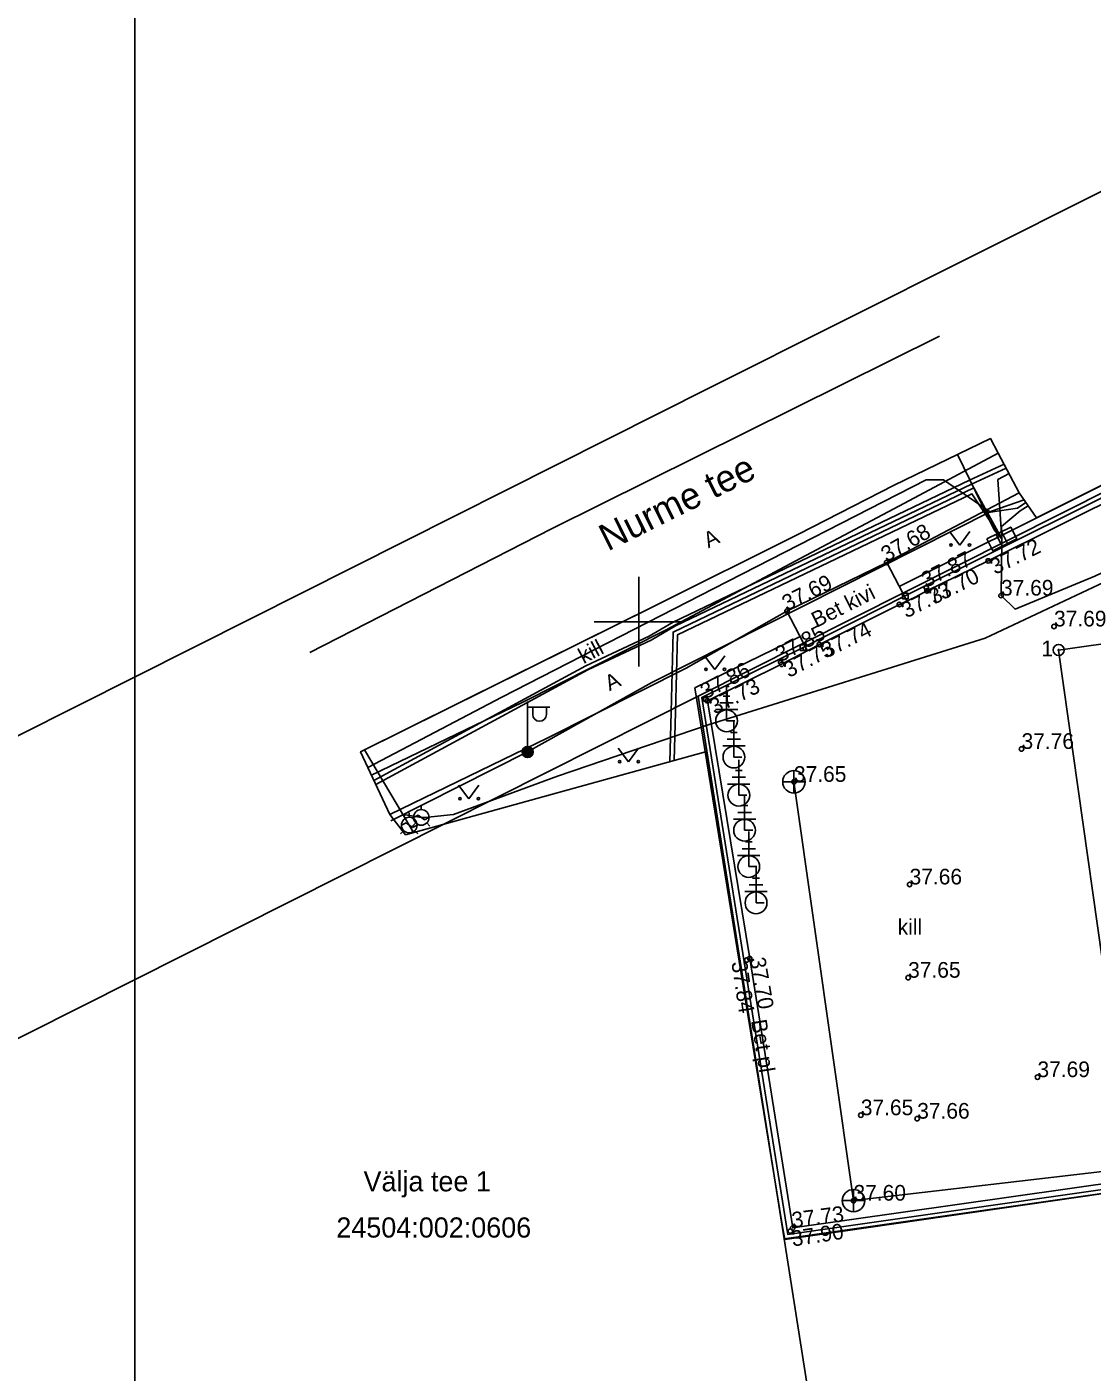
# Model space of a CAD drawing. Extents: x 551828 to 552309, y 6590593 to 6591152.
# Drawn here: x 552022.7 to 552070.2, y 6591016.5 to 6591076.6 of the extents above; entities that cross this region are included whole.
import ezdxf

# ---------------------------------------------------------------- set-up
doc = ezdxf.new("R2010")
doc.units = 0
for name, color, linetype in [('AED', 7, 'Continuous'), ('ELRAJATISMP', 7, 'Continuous'), ('GKAEV', 7, 'Continuous'), ('GTRASS', 7, 'Continuous'), ('HALJASTUS', 7, 'Continuous'), ('HOONE', 7, 'Continuous'), ('KKAEV', 7, 'Continuous'), ('KOORDPUNKT', 7, 'Continuous'), ('KORGUS-EH2000', 7, 'Continuous'), ('KPKAABEL', 7, 'Continuous'), ('MOOTPIIR', 7, 'Continuous'), ('MPKAABEL', 7, 'Continuous'), ('PIIR', 7, 'Continuous'), ('POST', 7, 'Continuous'), ('PUU', 7, 'Continuous'), ('RAJATIS', 7, 'Continuous'), ('SKTRASS', 7, 'Continuous'), ('TEE', 7, 'Continuous'), ('VORK', 7, 'Continuous'), ('VORMISTUS', 7, 'Continuous')]:
    doc.layers.add(name, color=color, linetype=linetype)

msp = doc.modelspace()

# ---------------------------------------------------------------- linework, layer by layer
at = {"layer": 'AED'}
for p, q in [((552057.329, 6591048.844), (552061.896, 6591051.151)), ((552061.771, 6591051.276), (552061.771, 6591051.026)), ((552061.771, 6591051.276), (552062.021, 6591051.276)), ((552062.021, 6591051.276), (552062.021, 6591051.026)), ((552061.771, 6591051.026), (552062.021, 6591051.026)), ((552057.204, 6591048.969), (552057.204, 6591048.719)), ((552057.204, 6591048.969), (552057.454, 6591048.969)), ((552057.204, 6591048.719), (552057.454, 6591048.719)), ((552057.454, 6591048.969), (552057.454, 6591048.719))]:
    msp.add_line(p, q, dxfattribs=at)
for points in [[(552147.637, 6591052.26), (552140.304, 6591080.517), (552139.66, 6591082.912), (552137.43, 6591081.846), (552130.717, 6591078.419), (552116.026, 6591074.952), (552103.814, 6591072.044), (552061.896, 6591051.151)], [(552149.845, 6591043.418), (552151.659, 6591036.289), (552099.026, 6591028.695), (552056.657, 6591022.632), (552052.805, 6591046.621), (552057.329, 6591048.844)]]:
    msp.add_lwpolyline(points, dxfattribs=at)
at = {"layer": 'ELRAJATISMP'}
for p, q in [((552065.954, 6591053.902), (552066.221, 6591053.368)), ((552066.196, 6591054.024), (552066.464, 6591053.49))]:
    msp.add_line(p, q, dxfattribs=at)
msp.add_lwpolyline([(552065.541, 6591053.695), (552066.609, 6591054.23), (552066.876, 6591053.697), (552065.809, 6591053.161)], close=True, dxfattribs=at)
at = {"layer": 'GKAEV'}
for p, q in [((552039.746, 6591041.268), (552039.746, 6591041.465)), ((552040.28, 6591041.61), (552040.28, 6591041.807)), ((552039.4, 6591040.918), (552039.607, 6591041.022)), ((552039.607, 6591041.022), (552039.885, 6591040.814)), ((552039.885, 6591040.814), (552040.092, 6591040.918)), ((552040.033, 6591041.013), (552039.893, 6591040.873)), ((552039.934, 6591041.26), (552040.141, 6591041.364)), ((552040.141, 6591041.364), (552040.419, 6591041.156)), ((552040.419, 6591041.156), (552040.626, 6591041.26)), ((552040.527, 6591041.013), (552040.667, 6591040.873)), ((552039.499, 6591040.671), (552039.359, 6591040.531)), ((552039.993, 6591040.671), (552040.133, 6591040.531))]:
    msp.add_line(p, q, dxfattribs=at)
for centre in [(552040.28, 6591041.26), (552039.746, 6591040.918)]:
    msp.add_circle(centre, 0.35, dxfattribs=at)
at = {"layer": 'GTRASS'}
for points in [[(552039.49, 6591041.34), (552039.58, 6591041.38), (552040.12, 6591041.29), (552040.28, 6591041.26), (552040.44, 6591041.25), (552041.72, 6591041.39), (552046.37, 6591043.11), (552053.09, 6591045.39), (552065.47, 6591049.26), (552076.35, 6591054.38), (552086.74, 6591059.24), (552096.54, 6591063.89), (552096.77, 6591063.92), (552097.394, 6591063.649), (552097.933, 6591063.194), (552097.957, 6591063.062), (552097.389, 6591062.977), (552097.402, 6591062.885)], [(552037.75, 6591044.286), (552039.49, 6591041.34), (552039.746, 6591040.918), (552039.931, 6591040.584)]]:
    msp.add_lwpolyline(points, dxfattribs=at)
at = {"layer": 'HALJASTUS'}
for p, q in [((552063.873, 6591054.03), (552064.336, 6591053.424)), ((552064.336, 6591053.424), (552064.782, 6591054.03)), ((552052.931, 6591048.481), (552053.394, 6591047.874)), ((552053.394, 6591047.874), (552053.84, 6591048.481)), ((552049.079, 6591044.356), (552049.543, 6591043.75)), ((552049.543, 6591043.75), (552049.988, 6591044.356)), ((552041.944, 6591042.701), (552042.408, 6591042.095)), ((552042.408, 6591042.095), (552042.853, 6591042.701))]:
    msp.add_line(p, q, dxfattribs=at)
for centre in [(552063.935, 6591053.424), (552064.764, 6591053.424), (552052.993, 6591047.874), (552053.822, 6591047.874), (552049.142, 6591043.75), (552049.971, 6591043.75), (552042.007, 6591042.095), (552042.835, 6591042.095)]:
    msp.add_circle(centre, 0.055, dxfattribs=at)
at = {"layer": 'HOONE'}
msp.add_lwpolyline([(552071.587, 6591028.635), (552068.745, 6591048.736), (552098.36, 6591052.94), (552096.972, 6591062.824), (552117.134, 6591065.69), (552121.395, 6591035.706)], close=True, dxfattribs=at)
at = {"layer": 'KKAEV'}
for p, q in [((552056.924, 6591042.35), (552056.924, 6591043.35)), ((552056.424, 6591042.85), (552057.424, 6591042.85)), ((552059.584, 6591023.647), (552059.584, 6591024.647)), ((552059.084, 6591024.147), (552060.084, 6591024.147))]:
    msp.add_line(p, q, dxfattribs=at)
for centre in [(552056.924, 6591042.85), (552059.584, 6591024.147)]:
    msp.add_circle(centre, 0.5, dxfattribs=at)
at = {"layer": 'KOORDPUNKT'}
for radius in [0.25, 0.025, 0.0221, 0.0191, 0.0161, 0.0132, 0.0102, 0.00726, 0.0043]:
    msp.add_circle((552068.745, 6591048.736), radius, dxfattribs=at)
at = {"layer": 'KORGUS-EH2000'}
for centre in [(552061.066, 6591052.646), (552065.598, 6591052.716), (552062.839, 6591051.51), (552062.864, 6591051.378), (552066.171, 6591051.167), (552056.612, 6591050.47), (552061.631, 6591050.768), (552068.539, 6591049.789), (552058.06, 6591048.98), (552056.331, 6591048.183), (552056.375, 6591048.099), (552052.978, 6591046.528), (552053.066, 6591046.467), (552067.088, 6591044.319), (552056.924, 6591042.85), (552062.089, 6591038.268), (552054.821, 6591034.893), (552054.95, 6591034.959), (552062.023, 6591034.102), (552067.799, 6591029.663), (552059.91, 6591027.962), (552062.429, 6591027.808), (552059.584, 6591024.147), (552056.764, 6591022.788), (552056.869, 6591022.928)]:
    msp.add_circle(centre, 0.1, dxfattribs=at)
at = {"layer": 'KPKAABEL'}
for points in [[(552066.31, 6591057.032), (552064.769, 6591056.329), (552051.536, 6591049.987), (552050.457, 6591049.357), (552047.63, 6591048.029), (552038.17, 6591042.91)], [(552066.406, 6591056.851), (552064.86, 6591056.145), (552051.63, 6591049.81), (552050.55, 6591049.18), (552047.72, 6591047.85), (552038.255, 6591042.729)]]:
    msp.add_lwpolyline(points, dxfattribs=at)
at = {"layer": 'MOOTPIIR'}
msp.add_lwpolyline([(552121.905, 6591031.76), (552098.767, 6591028.437), (552098.829, 6591027.951), (552097.324, 6591027.687), (552097.257, 6591028.201), (552070.742, 6591024.47), (552059.117, 6591022.785), (552056.51, 6591022.407), (552056.403, 6591023.066), (552054.752, 6591033.19), (552052.967, 6591044.185), (552039.584, 6591040.488), (552038.881, 6591041.392), (552037.568, 6591044.196), (552044.191, 6591047.481), (552050.676, 6591050.698), (552057.128, 6591053.914), (552061.407, 6591056.102), (552065.701, 6591058.181), (552066.051, 6591057.524), (552066.981, 6591055.761), (552067.763, 6591054.637), (552103.559, 6591072.502), (552116.628, 6591075.6)], dxfattribs=at)
at = {"layer": 'MPKAABEL'}
for points in [[(552066.209, 6591053.696), (552066.171, 6591051.167), (552066.803, 6591050.557), (552070.357, 6591052.028), (552089.564, 6591061.079), (552094.799, 6591063.511), (552095.695, 6591064.13), (552096.41, 6591064.875), (552097.511, 6591064.864), (552097.841, 6591063.973), (552098.05, 6591062.977)], [(552066.209, 6591053.696), (552065.872, 6591054.11), (552064.222, 6591057.465)], [(552066.209, 6591053.696), (552066.023, 6591056.349), (552066.528, 6591056.62)], [(552037.899, 6591043.489), (552043.884, 6591046.624), (552053.353, 6591051.478), (552062.822, 6591056.331), (552063.598, 6591056.338), (552065.705, 6591054.891), (552066.914, 6591055.076), (552067.286, 6591055.323)], [(552066.209, 6591053.696), (552064.959, 6591055.977), (552051.524, 6591049.537), (552051.442, 6591045.966), (552051.379, 6591043.747)], [(552038.915, 6591041.103), (552045.03, 6591044.183), (552050.575, 6591047.281), (552065.743, 6591054.935), (552067.204, 6591055.441)], [(552066.209, 6591053.696), (552064.87, 6591055.71), (552051.721, 6591049.41), (552051.642, 6591045.961), (552051.581, 6591043.802)], [(552067.384, 6591055.181), (552067.025, 6591054.945), (552066.186, 6591054.249), (552066.209, 6591053.696)]]:
    msp.add_lwpolyline(points, dxfattribs=at)
at = {"layer": 'PIIR'}
msp.add_lwpolyline([(551994.68, 6591017.51), (552041.41, 6591041.02), (552052.64, 6591046.67), (552103.56, 6591072.29), (552129.86, 6591078.57), (552139.81, 6591083.25), (552149.14, 6591087.65), (552143.71, 6591108.79), (552138.17, 6591106.07), (552120.12, 6591097.22), (552089.7, 6591078.79), (552070.79, 6591069.29), (552053.16, 6591060.44), (552032.69, 6591050.15), (552014.5, 6591041)], dxfattribs=at)
for points in [[(552052.64, 6591046.67), (552056.49, 6591022.44), (552152.01, 6591036.07), (552139.81, 6591083.25), (552129.86, 6591078.57), (552103.56, 6591072.29)], [(551832.17, 6590982.52), (551886.71, 6590842.14), (551918.59, 6590788.48), (551965, 6590795.13), (552016.25, 6590802.46), (552028.13, 6590804.16), (552077.63, 6590811.24), (552089.51, 6590812.93), (552088.6, 6590818.76), (552081.41, 6590864.37), (552072.84, 6590918.7), (552064.25, 6590973.06), (552056.49, 6591022.44), (552052.64, 6591046.67), (552041.41, 6591041.02), (551994.68, 6591017.51), (551983.25, 6591011.76), (551937.5, 6590988.73), (551835.15, 6590982.69)], [(552056.49, 6591022.44), (552064.25, 6590973.06), (552164.61, 6590987.36), (552152.01, 6591036.07)]]:
    msp.add_lwpolyline(points, close=True, dxfattribs=at)
at = {"layer": 'POST'}
for p, q in [((552045.03, 6591044.433), (552045.03, 6591046.433)), ((552045.03, 6591046.183), (552046.03, 6591046.183)), ((552045.257, 6591045.862), (552045.257, 6591046.183)), ((552045.869, 6591045.862), (552045.869, 6591046.183)), ((552045.03, 6591044.183), (552045.03, 6591044.183))]:
    msp.add_line(p, q, dxfattribs=at)
for radius in [0.25, 0.225, 0.2, 0.175, 0.15, 0.125, 0.1, 0.075, 0.05, 0.025]:
    msp.add_circle((552045.03, 6591044.183), radius, dxfattribs=at)
msp.add_arc((552045.563, 6591045.862), 0.306, 180, 0, dxfattribs=at)
at = {"layer": 'PUU'}
for p, q in [((552053.917, 6591045.574), (552053.917, 6591047.149)), ((552054.217, 6591046.374), (552053.617, 6591046.374)), ((552054.067, 6591046.674), (552053.767, 6591046.674)), ((552054.417, 6591046.074), (552053.417, 6591046.074)), ((552054.277, 6591045.574), (552053.917, 6591045.574)), ((552054.393, 6591045.057), (552054.093, 6591045.057)), ((552054.243, 6591043.957), (552054.243, 6591045.532)), ((552054.743, 6591044.457), (552053.743, 6591044.457)), ((552054.543, 6591044.757), (552053.943, 6591044.757)), ((552054.603, 6591043.957), (552054.243, 6591043.957)), ((552054.461, 6591042.253), (552054.461, 6591043.828)), ((552054.611, 6591043.353), (552054.311, 6591043.353)), ((552054.961, 6591042.753), (552053.961, 6591042.753)), ((552054.761, 6591043.053), (552054.161, 6591043.053)), ((552054.821, 6591042.253), (552054.461, 6591042.253)), ((552054.722, 6591040.687), (552054.722, 6591042.262)), ((552055.022, 6591041.487), (552054.422, 6591041.487)), ((552054.872, 6591041.787), (552054.572, 6591041.787)), ((552055.222, 6591041.187), (552054.222, 6591041.187)), ((552055.082, 6591040.687), (552054.722, 6591040.687)), ((552054.905, 6591039.064), (552054.905, 6591040.639)), ((552055.205, 6591039.864), (552054.605, 6591039.864)), ((552055.055, 6591040.164), (552054.755, 6591040.164)), ((552055.405, 6591039.564), (552054.405, 6591039.564)), ((552055.265, 6591039.064), (552054.905, 6591039.064)), ((552055.23, 6591037.447), (552055.23, 6591039.022)), ((552055.38, 6591038.547), (552055.08, 6591038.547)), ((552055.73, 6591037.947), (552054.73, 6591037.947)), ((552055.53, 6591038.247), (552054.93, 6591038.247)), ((552055.59, 6591037.447), (552055.23, 6591037.447))]:
    msp.add_line(p, q, dxfattribs=at)
at = {"layer": 'RAJATIS'}
for centre in [(552053.917, 6591045.574), (552054.243, 6591043.957), (552054.461, 6591042.253), (552054.722, 6591040.687), (552054.905, 6591039.064), (552055.23, 6591037.447)]:
    msp.add_circle(centre, 0.486, dxfattribs=at)
at = {"layer": 'SKTRASS'}
for p, q in [((552056.924, 6591042.85), (552059.584, 6591024.147)), ((552059.584, 6591024.147), (552097.953, 6591028.627))]:
    msp.add_line(p, q, dxfattribs=at)
at = {"layer": 'TEE'}
for p, q in [((552061.967, 6591050.928), (552061.066, 6591052.646)), ((552057.53, 6591048.702), (552056.612, 6591050.47))]:
    msp.add_line(p, q, dxfattribs=at)
for points in [[(552146.282, 6591054.85), (552147.086, 6591055.056), (552147.828, 6591052.159), (552148.048, 6591052.225), (552148.008, 6591052.359), (552139.991, 6591083.412), (552139.137, 6591083.215), (552130.577, 6591078.919), (552129.697, 6591078.698), (552103.559, 6591072.502), (552061.628, 6591051.575)], [(552122.699, 6591032.327), (552098.285, 6591028.866), (552098.373, 6591028.276), (552097.676, 6591028.158), (552097.572, 6591028.753), (552071.652, 6591025.036), (552056.869, 6591022.928), (552054.95, 6591034.959), (552053.066, 6591046.467), (552056.375, 6591048.099), (552058.06, 6591048.98), (552061.631, 6591050.768), (552062.335, 6591051.103), (552062.864, 6591051.378), (552065.598, 6591052.716), (552081.606, 6591060.679), (552096.222, 6591067.942), (552103.896, 6591071.784), (552116.575, 6591074.794)], [(552035.301, 6591048.632), (552046.095, 6591054.148), (552063.429, 6591062.756)], [(552037.568, 6591044.196), (552050.676, 6591050.698), (552057.128, 6591053.914), (552061.407, 6591056.102), (552065.701, 6591058.181)], [(552038.06, 6591043.146), (552044.791, 6591046.388), (552051.222, 6591049.636), (552057.458, 6591052.958), (552061.863, 6591055.291), (552066.051, 6591057.524)], [(552038.881, 6591041.392), (552045.927, 6591044.808), (552052.105, 6591047.921), (552056.612, 6591050.47), (552061.066, 6591052.646), (552063.533, 6591053.942), (552066.981, 6591055.761)], [(552057.2, 6591049.342), (552052.503, 6591047.042), (552054.752, 6591033.19), (552056.403, 6591023.066), (552056.51, 6591022.407), (552059.117, 6591022.785), (552070.742, 6591024.47), (552097.257, 6591028.201), (552097.324, 6591027.687), (552098.829, 6591027.951), (552098.767, 6591028.437), (552121.905, 6591031.76), (552151.303, 6591036.057), (552152.101, 6591036.283), (552150.21, 6591043.556)]]:
    msp.add_lwpolyline(points, dxfattribs=at)
at = {"layer": 'VORK'}
for p, q in [((552050, 6591052), (552050, 6591048)), ((552048, 6591050), (552052, 6591050))]:
    msp.add_line(p, q, dxfattribs=at)
at = {"layer": 'VORMISTUS'}
msp.add_lwpolyline([(552222.489, 6591112.824), (552027.489, 6591112.824), (552027.489, 6590970.474), (552222.489, 6590970.474)], close=True, dxfattribs=at)

# ---------------------------------------------------------------- texts
at = {"layer": 'KOORDPUNKT'}
msp.add_text('1', height=0.7, dxfattribs=at).set_placement((552067.976, 6591048.459))
at = {"layer": 'KORGUS-EH2000'}
for s, rotation, p in [('37.68', 29.89588, (552061.066, 6591052.646)), ('37.72', 26.21607, (552065.908, 6591052.088)), ('37.87', 26.72292, (552062.839, 6591051.51)), ('37.70', 26.66262, (552063.178, 6591050.753)), ('37.69', 26.47928, (552056.612, 6591050.47)), ('37.73', 26.63159, (552061.945, 6591050.142)), ('37.85', 27.95786, (552056.331, 6591048.183)), ('37.74', 27.06894, (552058.379, 6591048.356)), ('37.75', 28.05702, (552056.704, 6591047.481)), ('37.86', 27.92523, (552052.978, 6591046.528)), ('37.73', 26.54114, (552053.378, 6591045.841)), ('37.84', 278.59208, (552054.129, 6591034.789)), ('37.70', 279.76766, (552054.95, 6591034.959)), ('37.73', 7.32408, (552056.869, 6591022.928)), ('37.90', 8.69069, (552056.87, 6591022.096))]:
    msp.add_text(s, height=0.7, rotation=rotation, dxfattribs=at).set_placement(p)
for s, p in [('37.69', (552066.171, 6591051.167)), ('37.69', (552068.539, 6591049.789)), ('37.76', (552067.088, 6591044.319)), ('37.65', (552056.924, 6591042.85)), ('37.66', (552062.089, 6591038.268)), ('37.65', (552062.023, 6591034.102)), ('37.69', (552067.799, 6591029.663)), ('37.65', (552059.91, 6591027.962)), ('37.66', (552062.429, 6591027.808)), ('37.60', (552059.584, 6591024.147))]:
    msp.add_text(s, height=0.7, dxfattribs=at).set_placement(p)
at = {"layer": 'PIIR'}
for s, p in [('Välja tee 1', (552037.703, 6591024.561)), ('24504:002:0606', (552036.489, 6591022.498))]:
    msp.add_text(s, height=0.9, dxfattribs=at).set_placement(p)
at = {"layer": 'TEE'}
for s, height, rotation, p in [('Nurme tee', 1.2, 26.40982, (552048.612, 6591053.131)), ('A', 0.7, 26.0378, (552053.101, 6591053.274)), ('Bet kivi', 0.7, 26.7089, (552057.926, 6591049.72)), ('kill', 0.7, 28.04482, (552047.531, 6591048.103)), ('A', 0.7, 26.0378, (552048.691, 6591046.887)), ('Bet pl', 0.7, 279.22203, (552055.004, 6591032.188))]:
    msp.add_text(s, height=height, rotation=rotation, dxfattribs=at).set_placement(p)
msp.add_text('kill', height=0.7, dxfattribs=at).set_placement((552061.556, 6591036.024))

doc.saveas('drawing.dxf')
